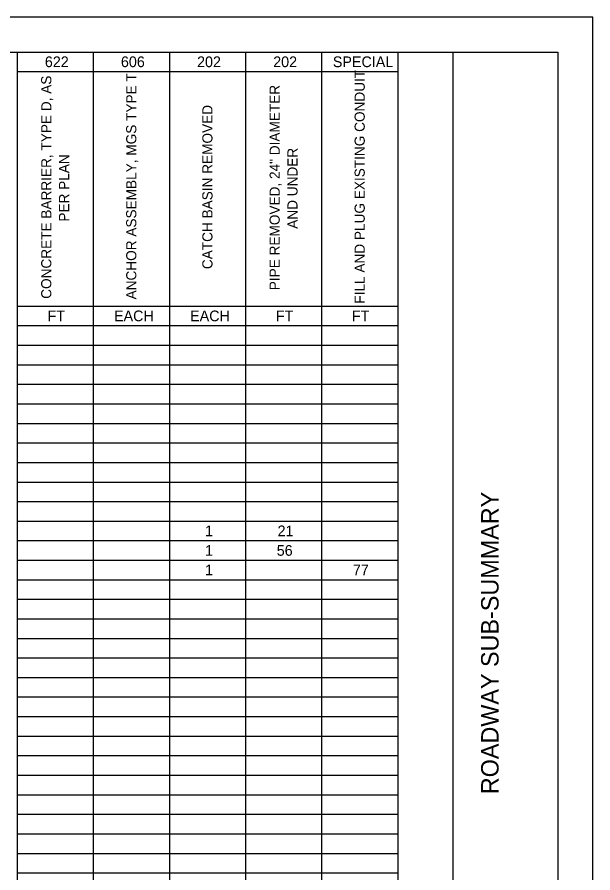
# Model space of a CAD drawing. Extents: x 0 to 34, y 0 to 22.
# Drawn here: x 25.76 to 34, y 9.75 to 22 of the extents above; entities that cross this region are included whole.
import ezdxf

# ---------------------------------------------------------------- set-up
doc = ezdxf.new("R2010")
doc.units = 0
for name, color, linetype in [('Default', 7, 'Continuous'), ('SH_Border', 7, 'Continuous'), ('SH_Cut_Line', 7, 'Continuous'), ('SH_Data', 7, 'Continuous')]:
    doc.layers.add(name, color=color, linetype=linetype)

msp = doc.modelspace()

# ---------------------------------------------------------------- linework, layer by layer
at = {"layer": 'Default'}
for p, q in [((25.757, 21.5), (26.847, 21.5)), ((25.757, 21.5), (25.757, 21.22)), ((26.847, 21.5), (27.937, 21.5)), ((26.847, 21.5), (26.847, 21.22)), ((27.937, 21.5), (29.026, 21.5)), ((27.937, 21.5), (27.937, 21.22)), ((29.026, 21.5), (31.206, 21.5)), ((29.026, 21.5), (29.026, 21.22)), ((30.116, 21.5), (30.116, 21.22)), ((31.206, 21.5), (31.206, 21.22)), ((25.757, 21.22), (26.847, 21.22)), ((25.757, 21.22), (25.757, 20.941)), ((26.847, 21.22), (27.937, 21.22)), ((26.847, 21.22), (26.847, 20.941)), ((27.937, 21.22), (29.026, 21.22)), ((27.937, 21.22), (27.937, 20.941)), ((29.026, 21.22), (31.206, 21.22)), ((29.026, 21.22), (29.026, 20.941)), ((30.116, 21.22), (30.116, 20.941)), ((31.206, 21.22), (31.206, 20.941)), ((25.757, 20.941), (25.757, 20.661)), ((26.847, 20.941), (26.847, 20.661)), ((27.937, 20.941), (27.937, 20.661)), ((29.026, 20.941), (29.026, 20.661)), ((30.116, 20.941), (30.116, 20.661)), ((31.206, 20.941), (31.206, 20.661)), ((25.757, 20.661), (25.757, 20.381)), ((26.847, 20.661), (26.847, 20.381)), ((27.937, 20.661), (27.937, 20.381)), ((29.026, 20.661), (29.026, 20.381)), ((30.116, 20.661), (30.116, 20.381)), ((31.206, 20.661), (31.206, 20.381)), ((25.757, 20.381), (25.757, 20.101)), ((26.847, 20.381), (26.847, 20.101)), ((27.937, 20.381), (27.937, 20.101)), ((29.026, 20.381), (29.026, 20.101)), ((30.116, 20.381), (30.116, 20.101)), ((31.206, 20.381), (31.206, 20.101)), ((25.757, 20.101), (25.757, 19.822)), ((26.847, 20.101), (26.847, 19.822)), ((27.937, 20.101), (27.937, 19.822)), ((29.026, 20.101), (29.026, 19.822)), ((30.116, 20.101), (30.116, 19.822)), ((31.206, 20.101), (31.206, 19.822)), ((25.757, 19.822), (25.757, 19.542)), ((26.847, 19.822), (26.847, 19.542)), ((27.937, 19.822), (27.937, 19.542)), ((29.026, 19.822), (29.026, 19.542)), ((30.116, 19.822), (30.116, 19.542)), ((31.206, 19.822), (31.206, 19.542)), ((25.757, 19.542), (25.757, 18.982)), ((26.847, 19.542), (26.847, 18.982)), ((27.937, 19.542), (27.937, 18.982)), ((29.026, 19.542), (29.026, 18.982)), ((30.116, 19.542), (30.116, 18.982)), ((31.206, 19.542), (31.206, 18.982)), ((25.757, 18.982), (25.757, 18.143)), ((26.847, 18.982), (26.847, 18.143)), ((27.937, 18.982), (27.937, 18.143)), ((29.026, 18.982), (29.026, 18.143)), ((30.116, 18.982), (30.116, 18.143)), ((31.206, 18.982), (31.206, 18.143)), ((25.757, 18.143), (25.757, 17.864)), ((26.847, 18.143), (26.847, 17.864)), ((27.937, 18.143), (27.937, 17.864)), ((29.026, 18.143), (29.026, 17.864)), ((30.116, 18.143), (30.116, 17.864)), ((31.206, 18.143), (31.206, 17.864)), ((25.757, 17.864), (26.847, 17.864)), ((25.757, 17.864), (25.757, 17.304)), ((26.847, 17.864), (27.937, 17.864)), ((26.847, 17.864), (26.847, 17.304)), ((27.937, 17.864), (29.026, 17.864)), ((27.937, 17.864), (27.937, 17.304)), ((29.026, 17.864), (31.206, 17.864)), ((29.026, 17.864), (29.026, 17.304)), ((30.116, 17.864), (30.116, 17.304)), ((31.206, 17.864), (31.206, 17.304)), ((25.757, 17.584), (26.847, 17.584)), ((26.847, 17.584), (27.937, 17.584)), ((27.937, 17.584), (29.026, 17.584)), ((29.026, 17.584), (31.206, 17.584)), ((25.757, 17.304), (26.847, 17.304)), ((25.757, 17.304), (25.757, 17.024)), ((26.847, 17.304), (27.937, 17.304)), ((26.847, 17.304), (26.847, 17.024)), ((27.937, 17.304), (29.026, 17.304)), ((27.937, 17.304), (27.937, 17.024)), ((29.026, 17.304), (31.206, 17.304)), ((29.026, 17.304), (29.026, 17.024)), ((30.116, 17.304), (30.116, 17.024)), ((31.206, 17.304), (31.206, 17.024)), ((25.757, 17.024), (26.847, 17.024)), ((25.757, 17.024), (25.757, 15.905)), ((26.847, 17.024), (27.937, 17.024)), ((26.847, 17.024), (26.847, 15.905)), ((27.937, 17.024), (29.026, 17.024)), ((27.937, 17.024), (27.937, 15.905)), ((29.026, 17.024), (31.206, 17.024)), ((29.026, 17.024), (29.026, 15.905)), ((30.116, 17.024), (30.116, 15.905)), ((31.206, 17.024), (31.206, 15.905)), ((25.757, 16.745), (26.847, 16.745)), ((26.847, 16.745), (27.937, 16.745)), ((27.937, 16.745), (29.026, 16.745)), ((29.026, 16.745), (31.206, 16.745)), ((25.757, 16.465), (26.847, 16.465)), ((26.847, 16.465), (27.937, 16.465)), ((27.937, 16.465), (29.026, 16.465)), ((29.026, 16.465), (31.206, 16.465)), ((25.757, 16.185), (26.847, 16.185)), ((26.847, 16.185), (27.937, 16.185)), ((27.937, 16.185), (29.026, 16.185)), ((29.026, 16.185), (31.206, 16.185)), ((25.757, 15.905), (26.847, 15.905)), ((25.757, 15.905), (25.757, 15.626)), ((26.847, 15.905), (27.937, 15.905)), ((26.847, 15.905), (26.847, 15.626)), ((27.937, 15.905), (29.026, 15.905)), ((27.937, 15.905), (27.937, 15.626)), ((29.026, 15.905), (31.206, 15.905)), ((29.026, 15.905), (29.026, 15.626)), ((30.116, 15.905), (30.116, 15.626)), ((31.206, 15.905), (31.206, 15.626)), ((25.757, 15.626), (26.847, 15.626)), ((25.757, 15.626), (25.757, 15.066)), ((26.847, 15.626), (27.937, 15.626)), ((26.847, 15.626), (26.847, 15.066)), ((27.937, 15.626), (29.026, 15.626)), ((27.937, 15.626), (27.937, 15.066)), ((29.026, 15.626), (31.206, 15.626)), ((29.026, 15.626), (29.026, 15.066)), ((30.116, 15.626), (30.116, 15.066)), ((31.206, 15.626), (31.206, 15.066)), ((25.757, 15.346), (26.847, 15.346)), ((26.847, 15.346), (27.937, 15.346)), ((27.937, 15.346), (29.026, 15.346)), ((29.026, 15.346), (31.206, 15.346)), ((25.757, 15.066), (26.847, 15.066)), ((25.757, 15.066), (25.757, 14.507)), ((26.847, 15.066), (27.937, 15.066)), ((26.847, 15.066), (26.847, 14.507)), ((27.937, 15.066), (29.026, 15.066)), ((27.937, 15.066), (27.937, 14.507)), ((29.026, 15.066), (31.206, 15.066)), ((29.026, 15.066), (29.026, 14.507)), ((30.116, 15.066), (30.116, 14.507)), ((31.206, 15.066), (31.206, 14.507)), ((25.757, 14.786), (26.847, 14.786)), ((26.847, 14.786), (27.937, 14.786)), ((27.937, 14.786), (29.026, 14.786)), ((29.026, 14.786), (31.206, 14.786)), ((25.757, 14.507), (26.847, 14.507)), ((25.757, 14.507), (25.757, 14.227)), ((26.847, 14.507), (27.937, 14.507)), ((26.847, 14.507), (26.847, 14.227)), ((27.937, 14.507), (29.026, 14.507)), ((27.937, 14.507), (27.937, 14.227)), ((29.026, 14.507), (31.206, 14.507)), ((29.026, 14.507), (29.026, 14.227)), ((30.116, 14.507), (30.116, 14.227)), ((31.206, 14.507), (31.206, 14.227)), ((25.757, 14.227), (26.847, 14.227)), ((25.757, 14.227), (25.757, 13.668)), ((26.847, 14.227), (27.937, 14.227)), ((26.847, 14.227), (26.847, 13.668)), ((27.937, 14.227), (29.026, 14.227)), ((27.937, 14.227), (27.937, 13.668)), ((29.026, 14.227), (31.206, 14.227)), ((29.026, 14.227), (29.026, 13.668)), ((30.116, 14.227), (30.116, 13.668)), ((31.206, 14.227), (31.206, 13.668)), ((25.757, 13.947), (26.847, 13.947)), ((26.847, 13.947), (27.937, 13.947)), ((27.937, 13.947), (29.026, 13.947)), ((29.026, 13.947), (31.206, 13.947)), ((25.757, 13.668), (26.847, 13.668)), ((25.757, 13.668), (25.757, 13.388)), ((26.847, 13.668), (27.937, 13.668)), ((26.847, 13.668), (26.847, 13.388)), ((27.937, 13.668), (29.026, 13.668)), ((27.937, 13.668), (27.937, 13.388)), ((29.026, 13.668), (31.206, 13.668)), ((29.026, 13.668), (29.026, 13.388)), ((30.116, 13.668), (30.116, 13.388)), ((31.206, 13.668), (31.206, 13.388)), ((25.757, 13.388), (26.847, 13.388)), ((25.757, 13.388), (25.757, 12.549)), ((26.847, 13.388), (27.937, 13.388)), ((26.847, 13.388), (26.847, 12.549)), ((27.937, 13.388), (29.026, 13.388)), ((27.937, 13.388), (27.937, 12.549)), ((29.026, 13.388), (31.206, 13.388)), ((29.026, 13.388), (29.026, 12.549)), ((30.116, 13.388), (30.116, 12.549)), ((31.206, 13.388), (31.206, 12.549)), ((25.757, 13.108), (26.847, 13.108)), ((26.847, 13.108), (27.937, 13.108)), ((27.937, 13.108), (29.026, 13.108)), ((29.026, 13.108), (31.206, 13.108)), ((25.757, 12.828), (26.847, 12.828)), ((26.847, 12.828), (27.937, 12.828)), ((27.937, 12.828), (29.026, 12.828)), ((29.026, 12.828), (31.206, 12.828)), ((25.757, 12.549), (26.847, 12.549)), ((25.757, 12.549), (25.757, 11.989)), ((26.847, 12.549), (27.937, 12.549)), ((26.847, 12.549), (26.847, 11.989)), ((27.937, 12.549), (29.026, 12.549)), ((27.937, 12.549), (27.937, 11.989)), ((29.026, 12.549), (31.206, 12.549)), ((29.026, 12.549), (29.026, 11.989)), ((30.116, 12.549), (30.116, 11.989)), ((31.206, 12.549), (31.206, 11.989)), ((25.757, 12.269), (26.847, 12.269)), ((26.847, 12.269), (27.937, 12.269)), ((27.937, 12.269), (29.026, 12.269)), ((29.026, 12.269), (31.206, 12.269)), ((25.757, 11.989), (26.847, 11.989)), ((25.757, 11.989), (25.757, 11.15)), ((26.847, 11.989), (27.937, 11.989)), ((26.847, 11.989), (26.847, 11.15)), ((27.937, 11.989), (29.026, 11.989)), ((27.937, 11.989), (27.937, 11.15)), ((29.026, 11.989), (31.206, 11.989)), ((29.026, 11.989), (29.026, 11.15)), ((30.116, 11.989), (30.116, 11.15)), ((31.206, 11.989), (31.206, 11.15)), ((25.757, 11.709), (26.847, 11.709)), ((26.847, 11.709), (27.937, 11.709)), ((27.937, 11.709), (29.026, 11.709)), ((29.026, 11.709), (31.206, 11.709)), ((25.757, 11.43), (26.847, 11.43)), ((26.847, 11.43), (27.937, 11.43)), ((27.937, 11.43), (29.026, 11.43)), ((29.026, 11.43), (31.206, 11.43)), ((25.757, 11.15), (26.847, 11.15)), ((25.757, 11.15), (25.757, 10.591)), ((26.847, 11.15), (27.937, 11.15)), ((26.847, 11.15), (26.847, 10.591)), ((27.937, 11.15), (29.026, 11.15)), ((27.937, 11.15), (27.937, 10.591)), ((29.026, 11.15), (31.206, 11.15)), ((29.026, 11.15), (29.026, 10.591)), ((30.116, 11.15), (30.116, 10.591)), ((31.206, 11.15), (31.206, 10.591)), ((25.757, 10.87), (26.847, 10.87)), ((26.847, 10.87), (27.937, 10.87)), ((27.937, 10.87), (29.026, 10.87)), ((29.026, 10.87), (31.206, 10.87)), ((25.757, 10.591), (26.847, 10.591)), ((25.757, 10.591), (25.757, 9.751)), ((26.847, 10.591), (27.937, 10.591)), ((26.847, 10.591), (26.847, 9.751)), ((27.937, 10.591), (29.026, 10.591)), ((27.937, 10.591), (27.937, 9.751)), ((29.026, 10.591), (31.206, 10.591)), ((29.026, 10.591), (29.026, 9.751)), ((30.116, 10.591), (30.116, 9.751)), ((31.206, 10.591), (31.206, 9.751)), ((25.757, 10.311), (26.847, 10.311)), ((26.847, 10.311), (27.937, 10.311)), ((27.937, 10.311), (29.026, 10.311)), ((29.026, 10.311), (31.206, 10.311)), ((25.757, 10.031), (26.847, 10.031)), ((26.847, 10.031), (27.937, 10.031)), ((27.937, 10.031), (29.026, 10.031)), ((29.026, 10.031), (31.206, 10.031)), ((25.757, 9.751), (26.847, 9.751)), ((25.757, 9.751), (25.757, 9.192)), ((26.847, 9.751), (27.937, 9.751)), ((26.847, 9.751), (26.847, 9.192)), ((27.937, 9.751), (29.026, 9.751)), ((27.937, 9.751), (27.937, 9.192)), ((29.026, 9.751), (31.206, 9.751)), ((29.026, 9.751), (29.026, 9.192)), ((30.116, 9.751), (30.116, 9.192)), ((31.206, 9.751), (31.206, 9.192))]:
    msp.add_line(p, q, dxfattribs=at)
at = {"layer": 'SH_Border'}
msp.add_line((32, 0.5), (32, 21.5), dxfattribs=at)
msp.add_lwpolyline([(1.5, 21.5), (33.5, 21.5), (33.5, 0.5), (1.5, 0.5)], close=True, dxfattribs=at)
at = {"layer": 'SH_Cut_Line'}
msp.add_lwpolyline([(0, 0), (34, 0), (34, 22), (0, 22)], close=True, dxfattribs=at)

# ---------------------------------------------------------------- texts
at = {"layer": 'Default'}
for s, height, p in [('622', 0.1532, (26.154, 21.284)), ('606', 0.1532, (27.243, 21.284)), ('202', 0.1532, (28.333, 21.284)), ('202', 0.1532, (29.423, 21.284)), ('SPECIAL', 0.1532, (30.277, 21.284)), ('FT', 0.1532, (26.192, 17.647)), ('EACH', 0.1532, (27.144, 17.647)), ('EACH', 0.1532, (28.234, 17.647)), ('FT', 0.1532, (29.461, 17.647)), ('FT', 0.1532, (30.551, 17.647)), ('1', 0.153, (28.447, 14.57)), ('21', 0.1532, (29.486, 14.57)), ('1', 0.153, (28.447, 14.29)), ('56', 0.1532, (29.474, 14.29)), ('1', 0.153, (28.447, 14.011)), ('77', 0.1532, (30.564, 14.011))]:
    msp.add_text(s, height=height, dxfattribs=at).set_placement(p)
for s, height, p in [('ANCHOR ASSEMBLY, MGS TYPE T', 0.14574, (27.464, 17.959)), ('FILL AND PLUG EXISTING CONDUIT', 0.14574, (30.734, 17.899)), ('CONCRETE BARRIER, TYPE D, AS ', 0.14574, (26.247, 17.968)), ('PIPE REMOVED, 24" DIAMETER ', 0.14574, (29.517, 18.091)), ('CATCH BASIN REMOVED', 0.14574, (28.554, 18.393)), ('AND UNDER', 0.1457, (29.772, 18.971)), ('PER PLAN', 0.1457, (26.502, 19.073))]:
    msp.add_text(s, height=height, rotation=90, dxfattribs=at).set_placement(p)
at = {"layer": 'SH_Data'}
msp.add_text('ROADWAY SUB-SUMMARY', height=0.25, rotation=90, dxfattribs=at).set_placement((32.65, 10.878))

doc.saveas('drawing.dxf')
